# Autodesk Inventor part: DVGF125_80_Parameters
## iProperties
Created: 2010-04
Part Number: DVGF125_80_Parameters
Document SubType Name: Modeling
Designer: TB
Density: 1 g/cm^3
Slaglengde: 100.000 mm
Vinkel_Plussport: 0.00 deg
Vinkel_Minusport: 0.00 deg
Forlengelse_rør: 0.000 mm
Author: TB
